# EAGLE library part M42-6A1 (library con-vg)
CONNECTOR male, 42 pins + 6 high current, type C, rows ABC, grid 2.54 mm
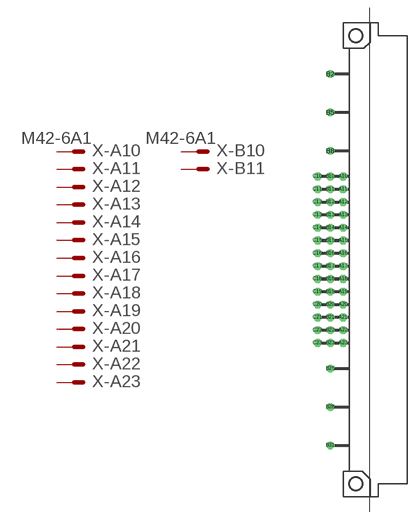
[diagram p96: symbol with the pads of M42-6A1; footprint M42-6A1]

Designator prefix X; gates -A10=MVAL -A11=MAL -A12=MAL -A13=MAL -A14=MAL -A15=MAL -A16=MAL -A17=MAL -A18=MAL -A19=MAL -A20=MAL -A21=MAL -A22=MAL -A23=MAL -B10=MVAL -B11=MAL -B12=MAL -B13=MAL -B14=MAL -B15=MAL -B16=MAL -B17=MAL -B18=MAL -B19=MAL -B20=MAL -B21=MAL -B22=MAL -B23=MAL -C10=MVAL -C11=MAL -C12=MAL -C13=MAL -C14=MAL -C15=MAL -C16=MAL -C17=MAL -C18=MAL -C19=MAL -C20=MAL -C21=MAL -C22=MAL -C23=MAL -B2=MAL-HIGHCUR -B5=MAL-HIGHCUR B8=MAL-HIGHCUR -B25=MAL-HIGHCUR -B28=MAL-HIGHCUR -B31=MAL-HIGHCUR

## M42-6A1  [M42-6A1]
A10  -A10:S  pas
A11  -A11:S  pas
A12  -A12:S  pas
A13  -A13:S  pas
A14  -A14:S  pas
A15  -A15:S  pas
A16  -A16:S  pas
A17  -A17:S  pas
A18  -A18:S  pas
A19  -A19:S  pas
A20  -A20:S  pas
A21  -A21:S  pas
A22  -A22:S  pas
A23  -A23:S  pas
B2  -B2:B  pas
B5  -B5:B  pas
B8  B8:B  pas
B10  -B10:S  pas
B11  -B11:S  pas
B12  -B12:S  pas
B13  -B13:S  pas
B14  -B14:S  pas
B15  -B15:S  pas
B16  -B16:S  pas
B17  -B17:S  pas
B18  -B18:S  pas
B19  -B19:S  pas
B20  -B20:S  pas
B21  -B21:S  pas
B22  -B22:S  pas
B23  -B23:S  pas
B25  -B25:B  pas
B28  -B28:B  pas
B31  -B31:B  pas
C10  -C10:S  pas
C11  -C11:S  pas
C12  -C12:S  pas
C13  -C13:S  pas
C14  -C14:S  pas
C15  -C15:S  pas
C16  -C16:S  pas
C17  -C17:S  pas
C18  -C18:S  pas
C19  -C19:S  pas
C20  -C20:S  pas
C21  -C21:S  pas
C22  -C22:S  pas
C23  -C23:S  pas

## Footprint M42-6A1 (pad centres in mm)
CONNECTOR male, 42 pins + 6 high current, type C, rows ABC, grid 2.54 mm
drill 1.016 octagon: A10 -2.54,16.51; A11 -2.54,13.97; A12 -2.54,11.43; A13 -2.54,8.89; A14 -2.54,6.35; A15 -2.54,3.81; A16 -2.54,1.27; A17 -2.54,-1.27; A18 -2.54,-3.81; A19 -2.54,-6.35; A20 -2.54,-8.89; A21 -2.54,-11.43; A22 -2.54,-13.97; A23 -2.54,-16.51; B2 -5.08,36.83; B5 -5.08,29.21; B8 -5.08,21.59; B10 -5.08,16.51; B11 -5.08,13.97; B12 -5.08,11.43; B13 -5.08,8.89; B14 -5.08,6.35; B15 -5.08,3.81; B16 -5.08,1.27; B17 -5.08,-1.27; B18 -5.08,-3.81; B19 -5.08,-6.35; B20 -5.08,-8.89; B21 -5.08,-11.43; B22 -5.08,-13.97; B23 -5.08,-16.51; B25 -5.08,-21.59; B28 -5.08,-29.21; B31 -5.08,-36.83; C10 -7.62,16.51; C11 -7.62,13.97; C12 -7.62,11.43; C13 -7.62,8.89; C14 -7.62,6.35; C15 -7.62,3.81; C16 -7.62,1.27; C17 -7.62,-1.27; C18 -7.62,-3.81; C19 -7.62,-6.35; C20 -7.62,-8.89; C21 -7.62,-11.43; C22 -7.62,-13.97; C23 -7.62,-16.51
hole 2.8 at 0,44.45
hole 2.8 at 0,-44.45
